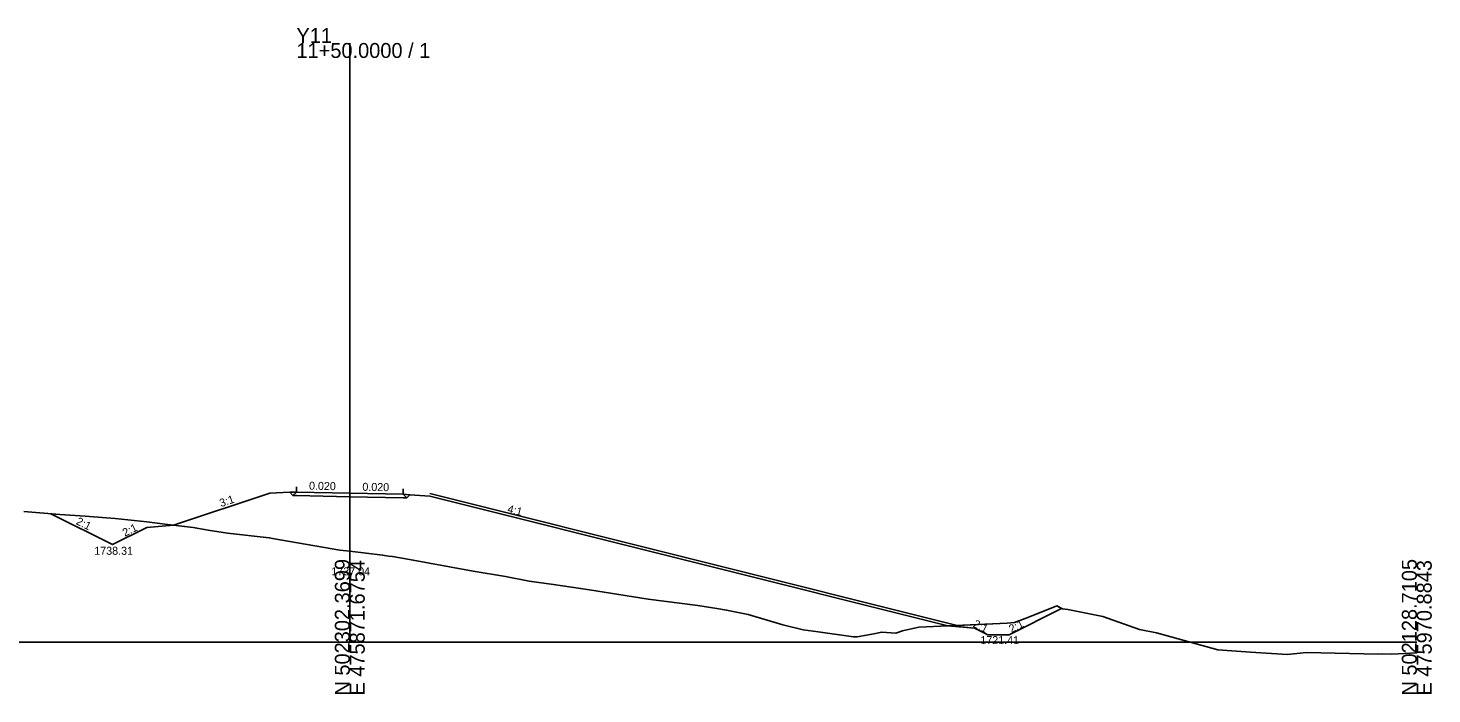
# Model space of a CAD drawing. Extents: x -76 to 353, y -10 to 8186.
# Drawn here: x 89.7 to 352.8, y 2990.3 to 3115.1 of the extents above; entities that cross this region are included whole.
import ezdxf

# ---------------------------------------------------------------- set-up
doc = ezdxf.new("R2010")
doc.units = 0
for name, color, linetype in [('Exist Cross Section Cell', 7, 'Continuous'), ('Exist XS Center Line Elevation Label', 7, 'Continuous'), ('Exist XS Ground Line', 7, 'Continuous'), ('Prop XS DDE', 7, 'Continuous'), ('Prop XS DDE Earthwork Shape', 7, 'Continuous'), ('Prop XS Ditch Standard Text', 7, 'Continuous'), ('Prop XS Dump Level', 7, 'Continuous'), ('Prop XS Earthwork Shape', 7, 'Continuous'), ('Prop XS EOT Tick Mark', 7, 'Continuous'), ('Prop XS Finish Grade', 7, 'Continuous'), ('Prop XS Finish Grade Earthwork', 7, 'Continuous'), ('Prop XS Finish Grade Pavement', 7, 'Continuous'), ('Prop XS Hydro Fill Slope Data', 7, 'Continuous'), ('Prop XS Pvmt Edge Slope', 7, 'Continuous'), ('Prop XS SE Text', 7, 'Continuous'), ('Prop XS Shoulder Borrow Shape', 7, 'Continuous'), ('Prop XS Side Slope Text', 7, 'Continuous'), ('Prop XS Subgrade Earthwork', 7, 'Continuous'), ('Scratch_Level_3', 7, 'Continuous'), ('Scratch_Level_6', 7, 'Continuous')]:
    doc.layers.add(name, color=color, linetype=linetype)

msp = doc.modelspace()

# ---------------------------------------------------------------- linework, layer by layer
at = {"layer": 'Exist Cross Section Cell'}
for p, q in [((150, 3000), (150, 3112.33)), ((-50, 3000), (150, 3000)), ((150, 3000), (350, 3000))]:
    msp.add_line(p, q, dxfattribs=at)
at = {"layer": 'Exist XS Ground Line'}
msp.add_lwpolyline([(88.89, 3024.53), (95.65, 3023.94), (100.41, 3023.61), (106.01, 3023.22), (111.93, 3022.54), (115.82, 3022.07), (120.67, 3021.49), (123.45, 3021.01), (127.07, 3020.42), (134.86, 3019.59), (135.54, 3019.47), (148.14, 3017.26), (150, 3017.04), (156.14, 3016.32), (157.28, 3016.12), (158, 3016.04), (160.49, 3015.65), (173.15, 3013.35), (179.19, 3012.3), (183.63, 3011.44), (188.19, 3010.84), (194.96, 3009.83), (205.93, 3008.06), (215.21, 3006.89), (218.83, 3006.32), (220.64, 3006.02), (224.68, 3005.21), (231.16, 3003.27), (235, 3002.31), (237.78, 3001.94), (244.4, 3001.02), (245.12, 3001.04), (248.22, 3001.59), (249.7, 3001.89), (252.37, 3001.72), (253.6, 3002.14), (256.69, 3002.82), (273.2, 3003.59), (274.62, 3003.7), (277.12, 3004.62), (282.54, 3006.79), (283.58, 3006.26), (284.6, 3006.11), (291.15, 3004.8), (298.03, 3002.36), (301.19, 3001.73), (312.72, 2998.58), (318.84, 2998.11), (325.73, 2997.71), (329.36, 2998.06), (342.75, 2997.78), (343.66, 2997.83), (345.3, 2997.78), (350, 2997.99)], dxfattribs=at)
at = {"layer": 'Prop XS DDE'}
for p, q in [((105.54, 3018.31), (93.98, 3024.09)), ((111.95, 3021.51), (105.54, 3018.31)), ((116.95, 3021.93), (111.95, 3021.51)), ((283.43, 3006.33), (273.59, 3001.41)), ((264.59, 3002.87), (262.09, 3003.08)), ((267.09, 3002.66), (262.09, 3003.08)), ((269.59, 3001.41), (267.09, 3002.66)), ((269.59, 3001.41), (273.59, 3001.41))]:
    msp.add_line(p, q, dxfattribs=at)
at = {"layer": 'Prop XS DDE Earthwork Shape'}
for points in [[(116.95, 3021.93), (111.95, 3021.51), (105.54, 3018.31), (93.98, 3024.09), (95.65, 3023.94), (100.41, 3023.61), (106.01, 3023.22), (111.93, 3022.54), (115.82, 3022.07)], [(111.95, 3021.51), (105.54, 3018.31), (93.98, 3024.09), (95.65, 3023.94), (100.41, 3023.61), (106.01, 3023.22), (111.93, 3022.54), (115.82, 3022.07), (116.95, 3021.93)], [(264.59, 3002.87), (267.09, 3002.66), (269.59, 3001.41), (273.59, 3001.41), (283.43, 3006.33), (282.54, 3006.79), (277.12, 3004.62), (274.62, 3003.7), (273.2, 3003.59), (262.09, 3003.08)], [(269.59, 3001.41), (267.09, 3002.66), (264.59, 3002.87), (262.09, 3003.08), (273.2, 3003.59), (274.62, 3003.7), (277.12, 3004.62), (282.54, 3006.79), (283.43, 3006.33), (273.59, 3001.41)]]:
    msp.add_lwpolyline(points, close=True, dxfattribs=at)
at = {"layer": 'Prop XS Dump Level'}
for p, q in [((140, 3028.15), (150, 3027.95)), ((150, 3027.95), (160, 3027.75))]:
    msp.add_line(p, q, dxfattribs=at)
at = {"layer": 'Prop XS Earthwork Shape'}
msp.add_lwpolyline([(139.35, 3027.5), (138.74, 3028.1), (135, 3027.95), (116.95, 3021.93), (120.67, 3021.49), (123.45, 3021.01), (127.07, 3020.42), (134.86, 3019.59), (135.54, 3019.47), (148.14, 3017.26), (150, 3017.04), (156.14, 3016.32), (157.28, 3016.12), (158, 3016.04), (160.49, 3015.65), (173.15, 3013.35), (179.19, 3012.3), (183.63, 3011.44), (188.19, 3010.84), (194.96, 3009.83), (205.93, 3008.06), (215.21, 3006.89), (218.83, 3006.32), (220.64, 3006.02), (224.68, 3005.21), (231.16, 3003.27), (235, 3002.31), (237.78, 3001.94), (244.4, 3001.02), (245.12, 3001.04), (248.22, 3001.59), (249.7, 3001.89), (252.37, 3001.72), (253.6, 3002.14), (256.69, 3002.82), (262.09, 3003.08), (165, 3027.35), (161.26, 3027.65), (160.68, 3027.07), (160, 3027.08), (150, 3027.28), (140, 3027.48)], close=True, dxfattribs=at)
at = {"layer": 'Prop XS EOT Tick Mark'}
for p, q in [((140, 3028.15), (140, 3029.15)), ((160, 3027.75), (160, 3028.75))]:
    msp.add_line(p, q, dxfattribs=at)
at = {"layer": 'Prop XS Finish Grade'}
for p, q in [((140, 3028.15), (138.74, 3028.1)), ((160, 3027.75), (161.26, 3027.65))]:
    msp.add_line(p, q, dxfattribs=at)
at = {"layer": 'Prop XS Finish Grade Earthwork'}
for p, q in [((135, 3027.95), (116.95, 3021.93)), ((138.74, 3028.1), (135, 3027.95)), ((161.26, 3027.65), (165, 3027.35)), ((165, 3027.35), (262.09, 3003.08))]:
    msp.add_line(p, q, dxfattribs=at)
at = {"layer": 'Prop XS Finish Grade Pavement'}
for p, q in [((140, 3028.15), (150, 3027.95)), ((150, 3027.95), (160, 3027.75))]:
    msp.add_line(p, q, dxfattribs=at)
at = {"layer": 'Prop XS Hydro Fill Slope Data'}
for p, q in [((135, 3027.95), (116.95, 3021.93)), ((165, 3027.35), (262.09, 3003.08))]:
    msp.add_line(p, q, dxfattribs=at)
at = {"layer": 'Prop XS Pvmt Edge Slope'}
for p, q in [((140, 3028.15), (139.35, 3027.5)), ((160, 3027.75), (160.68, 3027.07))]:
    msp.add_line(p, q, dxfattribs=at)
at = {"layer": 'Prop XS Shoulder Borrow Shape'}
for points in [[(140, 3028.15), (139.35, 3027.5), (138.74, 3028.1)], [(140, 3028.15), (139.35, 3027.5), (138.74, 3028.1)], [(160.68, 3027.07), (161.26, 3027.65), (160, 3027.75)], [(160.68, 3027.07), (161.26, 3027.65), (160, 3027.75)]]:
    msp.add_lwpolyline(points, close=True, dxfattribs=at)
at = {"layer": 'Prop XS Subgrade Earthwork'}
for p, q in [((139.35, 3027.5), (138.74, 3028.1)), ((140, 3027.48), (139.35, 3027.5)), ((150, 3027.28), (140, 3027.48)), ((160, 3027.08), (150, 3027.28)), ((160, 3027.08), (160.68, 3027.07)), ((160.68, 3027.07), (161.26, 3027.65))]:
    msp.add_line(p, q, dxfattribs=at)
at = {"layer": 'Scratch_Level_3'}
for p, q in [((93.98, 3024.09), (105.54, 3018.31)), ((105.54, 3018.31), (111.95, 3021.51)), ((111.95, 3021.51), (116.95, 3021.93)), ((116.95, 3021.93), (115.82, 3022.07)), ((273.59, 3001.41), (283.43, 3006.33)), ((283.43, 3006.33), (282.54, 3006.79)), ((263.87, 3003.16), (262.09, 3003.08)), ((262.09, 3003.08), (264.59, 3002.87)), ((263.87, 3003.16), (263.87, 3003.16)), ((264.59, 3002.87), (267.09, 3002.66)), ((267.09, 3002.66), (269.59, 3001.41)), ((269.59, 3001.41), (273.59, 3001.41))]:
    msp.add_line(p, q, dxfattribs=at)
for points in [[(115.82, 3022.07), (111.93, 3022.54), (106.01, 3023.22), (100.41, 3023.61), (95.65, 3023.94), (93.98, 3024.09)], [(282.54, 3006.79), (277.12, 3004.62), (274.62, 3003.7), (273.2, 3003.59), (263.87, 3003.16)], [(262.09, 3003.08), (262.09, 3003.08)], [(263.87, 3003.16), (263.87, 3003.16)]]:
    msp.add_lwpolyline(points, dxfattribs=at)
at = {"layer": 'Scratch_Level_6'}
msp.add_line((165, 3027.87), (263.87, 3003.16), dxfattribs=at)

# ---------------------------------------------------------------- texts
at = {"layer": 'Exist Cross Section Cell'}
for s, p in [('Y11', (140, 3112.33)), ('11+50.0000 / 1', (140, 3109.53))]:
    msp.add_text(s, height=2.8, dxfattribs=at).set_placement(p)
for s, p in [('N 502302.3699', (150, 2990)), ('E 475871.6754', (152.8, 2990)), ('N 502128.7105', (350, 2990)), ('E 475970.8843', (352.8, 2990))]:
    msp.add_text(s, height=2.8, rotation=90, dxfattribs=at).set_placement(p)
at = {"layer": 'Exist XS Center Line Elevation Label'}
msp.add_text('1737.04', height=1.5, dxfattribs=at).set_placement((146.55, 3012.54))
at = {"layer": 'Prop XS Ditch Standard Text'}
for s, p in [('1738.31', (102.11, 3016.39)), ('1721.41', (268.2, 2999.64))]:
    msp.add_text(s, height=1.5, dxfattribs=at).set_placement(p)
at = {"layer": 'Prop XS Dump Level'}
for p in [(135, 3027.91), (165, 3027.31)]:
    msp.add_text('Case1', height=0.04, dxfattribs=at).set_placement(p)
at = {"layer": 'Prop XS SE Text'}
for p in [(142.35, 3028.6), (152.35, 3028.4)]:
    msp.add_text('0.020', height=1.5, rotation=358.8542, dxfattribs=at).set_placement(p)
at = {"layer": 'Prop XS Side Slope Text'}
for s, rotation, p in [('3:1', 18.4349, (125.86, 3025.31)), ('4:1', 345.9638, (179.43, 3024.34)), ('2:1', 333.4349, (98.56, 3022.19)), ('2:1', 26.5651, (107.86, 3019.75)), ('2:1', 333.4349, (266.69, 3002.96)), ('2:1', 26.5651, (274.01, 3001.71))]:
    msp.add_text(s, height=1.5, rotation=rotation, dxfattribs=at).set_placement(p)

doc.saveas('drawing.dxf')
